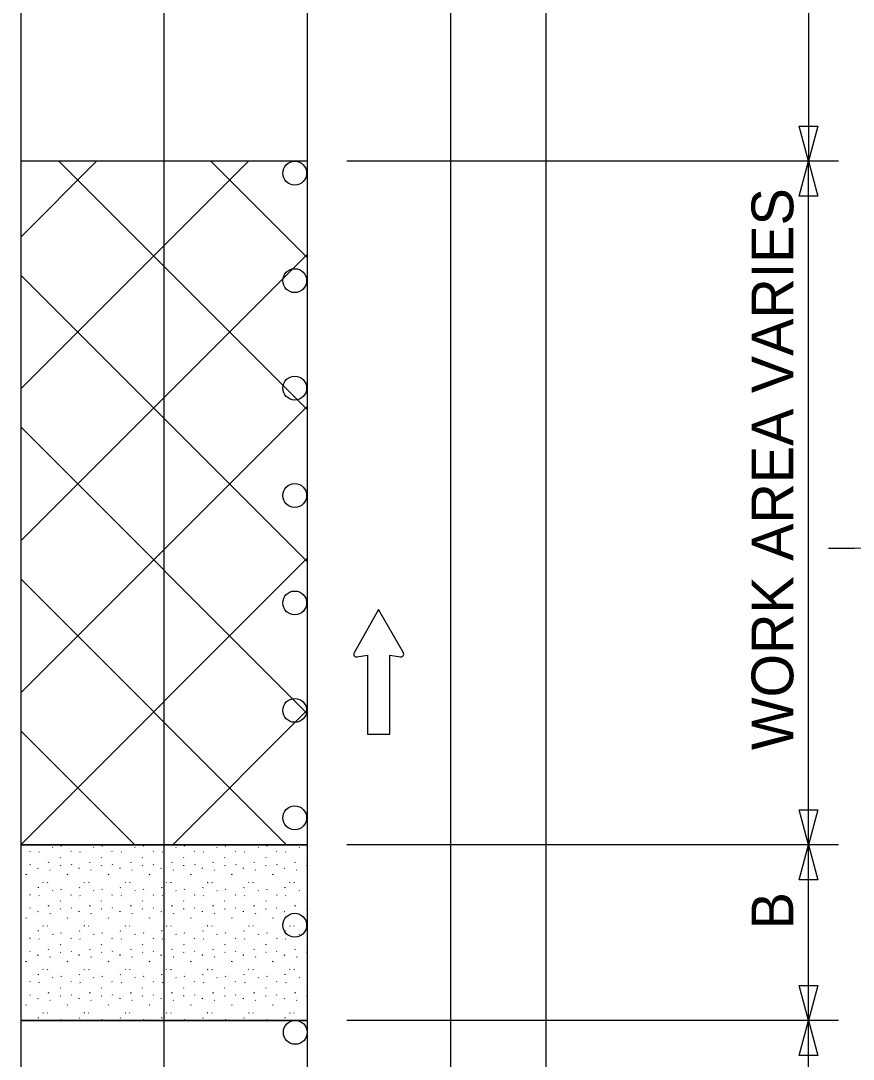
# Model space of a CAD drawing. Extents: x 16553 to 18478, y 5759 to 7026.
# Drawn here: x 16887.7 to 17027.1, y 6687.7 to 6861.7 of the extents above; entities that cross this region are included whole.
import ezdxf

# ---------------------------------------------------------------- set-up
doc = ezdxf.new("R2010")
doc.units = 0
for name, color, linetype in [('ALI_LEGAL_EX', 7, 'Continuous'), ('MT_SCRATCH_LEVEL_A', 7, 'Continuous'), ('MT_SCRATCH_LEVEL_E', 7, 'Continuous'), ('PAVT_EDGE_EX', 7, 'Continuous'), ('TRAFFIC_SIGNS_PR', 7, 'Continuous'), ('TYPICAL_TEXT_DIMEN_PR', 7, 'Continuous')]:
    doc.layers.add(name, color=color, linetype=linetype)

msp = doc.modelspace()

# ---------------------------------------------------------------- linework, layer by layer
at = {"layer": 'ALI_LEGAL_EX'}
for p, q in [((16911.66, 7026.35), (16911.66, 6197.16)), ((16935.66, 7026.35), (16935.66, 6197.16)), ((16935.66, 7026.35), (16935.66, 6197.16))]:
    msp.add_line(p, q, dxfattribs=at)
for points in [[(16911.66, 6826.35), (16911.66, 6801.35)], [(16935.66, 6826.35), (16935.66, 6801.35)], [(16911.66, 6726.35), (16911.66, 6701.35)], [(16935.66, 6726.35), (16935.66, 6701.35)]]:
    msp.add_lwpolyline(points, dxfattribs=at)
at = {"layer": 'MT_SCRATCH_LEVEL_A'}
for p, q in [((16935.66, 6838.16), (16887.66, 6838.16)), ((16935.66, 6723.62), (16887.66, 6723.62)), ((16935.66, 6694.2), (16887.66, 6694.2))]:
    msp.add_line(p, q, dxfattribs=at)
at = {"layer": 'MT_SCRATCH_LEVEL_E'}
for p, q in [((16947.62, 6763.02), (16943.51, 6755.78)), ((16951.77, 6755.78), (16947.62, 6763.02)), ((16943.99, 6755.1), (16945.77, 6755.41)), ((16945.77, 6755.41), (16945.77, 6742.15)), ((16949.51, 6742.15), (16949.51, 6755.41)), ((16949.51, 6755.41), (16951.29, 6755.1)), ((16945.77, 6742.15), (16949.51, 6742.15))]:
    msp.add_line(p, q, dxfattribs=at)
for centre, start, end in [((16943.92, 6755.56), 150.4248, 279.9638), ((16951.36, 6755.56), 260.0362, 29.7731)]:
    msp.add_arc(centre, 0.463, start, end, dxfattribs=at)
at = {"layer": 'PAVT_EDGE_EX'}
for p, q in [((16887.66, 6926.66), (16887.66, 6223.96)), ((16959.66, 6926.66), (16959.66, 6223.96)), ((16975.66, 6926.66), (16975.66, 6223.96)), ((16935.66, 6838.16), (16887.66, 6838.16)), ((16887.66, 6838.16), (16887.66, 6723.62)), ((16887.66, 6825.45), (16900.38, 6838.16)), ((16887.66, 6799.99), (16925.83, 6838.16)), ((16935.66, 6796.54), (16894.04, 6838.16)), ((16935.66, 6822), (16919.5, 6838.16)), ((16887.66, 6774.54), (16935.66, 6822.54)), ((16935.66, 6771.08), (16887.66, 6819.08)), ((16887.66, 6749.08), (16935.66, 6797.08)), ((16935.66, 6745.63), (16887.66, 6793.63)), ((16887.66, 6723.62), (16935.66, 6771.62)), ((16932.21, 6723.62), (16887.66, 6768.17)), ((16913.12, 6723.62), (16935.66, 6746.17)), ((16906.76, 6723.62), (16887.66, 6742.72)), ((16887.66, 6723.62), (16935.66, 6723.62)), ((16935.66, 6723.62), (16887.66, 6723.62)), ((16887.66, 6723.62), (16887.66, 6694.2)), ((16887.66, 6723.62), (16887.66, 6723.62)), ((16892.98, 6723.25), (16893.03, 6723.18)), ((16894.43, 6723.4), (16894.48, 6723.52)), ((16899.87, 6723.25), (16899.92, 6723.18)), ((16901.32, 6723.4), (16901.37, 6723.52)), ((16906.76, 6723.25), (16906.81, 6723.18)), ((16908.21, 6723.4), (16908.26, 6723.52)), ((16913.64, 6723.25), (16913.69, 6723.18)), ((16915.09, 6723.4), (16915.14, 6723.52)), ((16920.53, 6723.25), (16920.58, 6723.18)), ((16921.98, 6723.4), (16922.03, 6723.52)), ((16927.42, 6723.25), (16927.47, 6723.18)), ((16928.87, 6723.4), (16928.92, 6723.52)), ((16934.31, 6723.25), (16934.36, 6723.18)), ((16889.16, 6722.57), (16889.21, 6722.5)), ((16890.69, 6722.44), (16890.74, 6722.36)), ((16894.26, 6721.52), (16894.31, 6721.44)), ((16896.05, 6722.57), (16896.1, 6722.5)), ((16897.58, 6722.44), (16897.63, 6722.36)), ((16901.15, 6721.52), (16901.2, 6721.44)), ((16902.94, 6722.57), (16902.99, 6722.5)), ((16904.47, 6722.44), (16904.52, 6722.36)), ((16908.03, 6721.52), (16908.08, 6721.44)), ((16909.82, 6722.57), (16909.88, 6722.5)), ((16911.35, 6722.44), (16911.4, 6722.36)), ((16914.92, 6721.52), (16914.97, 6721.44)), ((16916.71, 6722.57), (16916.76, 6722.5)), ((16918.24, 6722.44), (16918.29, 6722.36)), ((16921.81, 6721.52), (16921.86, 6721.44)), ((16923.6, 6722.57), (16923.65, 6722.5)), ((16925.13, 6722.44), (16925.18, 6722.36)), ((16928.7, 6721.52), (16928.75, 6721.44)), ((16930.49, 6722.57), (16930.54, 6722.5)), ((16932.02, 6722.44), (16932.07, 6722.36)), ((16935.58, 6721.52), (16935.64, 6721.44)), ((16889.21, 6720.37), (16889.26, 6720.29)), ((16890.49, 6719.79), (16890.5, 6719.67)), ((16892.33, 6720.65), (16892.38, 6720.76)), ((16892.52, 6719.45), (16892.57, 6719.37)), ((16894.3, 6720.11), (16894.35, 6720.23)), ((16896.1, 6720.37), (16896.15, 6720.29)), ((16897.38, 6719.79), (16897.39, 6719.67)), ((16899.22, 6720.65), (16899.27, 6720.76)), ((16899.41, 6719.45), (16899.46, 6719.37)), ((16901.19, 6720.11), (16901.24, 6720.23)), ((16902.99, 6720.37), (16903.04, 6720.29)), ((16904.27, 6719.79), (16904.28, 6719.67)), ((16906.11, 6720.65), (16906.16, 6720.76)), ((16906.3, 6719.45), (16906.35, 6719.37)), ((16908.08, 6720.11), (16908.13, 6720.23)), ((16909.87, 6720.37), (16909.92, 6720.29)), ((16911.15, 6719.79), (16911.17, 6719.67)), ((16912.99, 6720.65), (16913.05, 6720.76)), ((16913.18, 6719.45), (16913.24, 6719.37)), ((16914.96, 6720.11), (16915.01, 6720.23)), ((16916.76, 6720.37), (16916.81, 6720.29)), ((16918.04, 6719.79), (16918.05, 6719.67)), ((16919.88, 6720.65), (16919.93, 6720.76)), ((16920.07, 6719.45), (16920.12, 6719.37)), ((16921.85, 6720.11), (16921.9, 6720.23)), ((16923.65, 6720.37), (16923.7, 6720.29)), ((16924.93, 6719.79), (16924.94, 6719.67)), ((16926.77, 6720.65), (16926.82, 6720.76)), ((16926.96, 6719.45), (16927.01, 6719.37)), ((16928.74, 6720.11), (16928.79, 6720.23)), ((16930.53, 6720.37), (16930.59, 6720.29)), ((16931.82, 6719.79), (16931.83, 6719.67)), ((16933.66, 6720.65), (16933.71, 6720.76)), ((16933.85, 6719.45), (16933.9, 6719.37)), ((16935.63, 6720.11), (16935.66, 6720.2)), ((16888.59, 6718.61), (16888.64, 6718.73)), ((16895.48, 6718.61), (16895.53, 6718.73)), ((16902.37, 6718.61), (16902.42, 6718.73)), ((16909.25, 6718.61), (16909.31, 6718.73)), ((16916.14, 6718.61), (16916.19, 6718.73)), ((16923.03, 6718.61), (16923.08, 6718.73)), ((16929.92, 6718.61), (16929.97, 6718.73)), ((16890.61, 6716.42), (16890.66, 6716.53)), ((16891.38, 6717.38), (16891.43, 6717.3)), ((16892.11, 6717.35), (16892.16, 6717.27)), ((16892.98, 6715.97), (16893.03, 6715.89)), ((16894.43, 6716.12), (16894.48, 6716.24)), ((16897.5, 6716.42), (16897.55, 6716.53)), ((16898.26, 6717.38), (16898.31, 6717.3)), ((16899, 6717.35), (16899.05, 6717.27)), ((16899.87, 6715.97), (16899.92, 6715.89)), ((16901.32, 6716.12), (16901.37, 6716.24)), ((16904.39, 6716.42), (16904.44, 6716.53)), ((16905.15, 6717.38), (16905.2, 6717.3)), ((16905.89, 6717.35), (16905.94, 6717.27)), ((16906.76, 6715.97), (16906.81, 6715.89)), ((16908.21, 6716.12), (16908.26, 6716.24)), ((16911.27, 6716.42), (16911.33, 6716.53)), ((16912.04, 6717.38), (16912.09, 6717.3)), ((16912.78, 6717.35), (16912.83, 6717.27)), ((16913.64, 6715.97), (16913.69, 6715.89)), ((16915.09, 6716.12), (16915.14, 6716.24)), ((16918.16, 6716.42), (16918.21, 6716.53)), ((16918.92, 6717.38), (16918.98, 6717.3)), ((16919.66, 6717.35), (16919.71, 6717.27)), ((16920.53, 6715.97), (16920.58, 6715.89)), ((16921.98, 6716.12), (16922.03, 6716.24)), ((16925.05, 6716.42), (16925.1, 6716.53)), ((16925.81, 6717.38), (16925.86, 6717.3)), ((16926.55, 6717.35), (16926.6, 6717.27)), ((16927.42, 6715.97), (16927.47, 6715.89)), ((16928.87, 6716.12), (16928.92, 6716.24)), ((16931.94, 6716.42), (16931.99, 6716.53)), ((16932.7, 6717.38), (16932.75, 6717.3)), ((16933.44, 6717.35), (16933.49, 6717.27)), ((16934.31, 6715.97), (16934.36, 6715.89)), ((16889.16, 6715.29), (16889.21, 6715.21)), ((16890.69, 6715.15), (16890.74, 6715.07)), ((16894.26, 6714.23), (16894.31, 6714.15)), ((16896.05, 6715.29), (16896.1, 6715.21)), ((16897.58, 6715.15), (16897.63, 6715.07)), ((16901.15, 6714.23), (16901.2, 6714.15)), ((16902.94, 6715.29), (16902.99, 6715.21)), ((16904.47, 6715.15), (16904.52, 6715.07)), ((16908.03, 6714.23), (16908.08, 6714.15)), ((16909.82, 6715.29), (16909.88, 6715.21)), ((16911.35, 6715.15), (16911.4, 6715.07)), ((16914.92, 6714.23), (16914.97, 6714.15)), ((16916.71, 6715.29), (16916.76, 6715.21)), ((16918.24, 6715.15), (16918.29, 6715.07)), ((16921.81, 6714.23), (16921.86, 6714.15)), ((16923.6, 6715.29), (16923.65, 6715.21)), ((16925.13, 6715.15), (16925.18, 6715.07)), ((16928.7, 6714.23), (16928.75, 6714.15)), ((16930.49, 6715.29), (16930.54, 6715.21)), ((16932.02, 6715.15), (16932.07, 6715.07)), ((16935.58, 6714.23), (16935.64, 6714.15)), ((16889.21, 6713.08), (16889.26, 6713)), ((16890.49, 6712.51), (16890.5, 6712.39)), ((16892.33, 6713.36), (16892.38, 6713.48)), ((16894.3, 6712.83), (16894.35, 6712.95)), ((16896.1, 6713.08), (16896.15, 6713)), ((16897.38, 6712.51), (16897.39, 6712.39)), ((16899.22, 6713.36), (16899.27, 6713.48)), ((16901.19, 6712.83), (16901.24, 6712.95)), ((16902.99, 6713.08), (16903.04, 6713)), ((16904.27, 6712.51), (16904.28, 6712.39)), ((16906.11, 6713.36), (16906.16, 6713.48)), ((16908.08, 6712.83), (16908.13, 6712.95)), ((16909.87, 6713.08), (16909.92, 6713)), ((16911.15, 6712.51), (16911.17, 6712.39)), ((16912.99, 6713.36), (16913.05, 6713.48)), ((16914.96, 6712.83), (16915.01, 6712.95)), ((16916.76, 6713.08), (16916.81, 6713)), ((16918.04, 6712.51), (16918.05, 6712.39)), ((16919.88, 6713.36), (16919.93, 6713.48)), ((16921.85, 6712.83), (16921.9, 6712.95)), ((16923.65, 6713.08), (16923.7, 6713)), ((16924.93, 6712.51), (16924.94, 6712.39)), ((16926.77, 6713.36), (16926.82, 6713.48)), ((16928.74, 6712.83), (16928.79, 6712.95)), ((16930.53, 6713.08), (16930.59, 6713)), ((16931.82, 6712.51), (16931.83, 6712.39)), ((16933.66, 6713.36), (16933.71, 6713.48)), ((16935.63, 6712.83), (16935.66, 6712.92)), ((16888.59, 6711.33), (16888.64, 6711.44)), ((16892.52, 6712.16), (16892.57, 6712.08)), ((16895.48, 6711.33), (16895.53, 6711.44)), ((16899.41, 6712.16), (16899.46, 6712.08)), ((16902.37, 6711.33), (16902.42, 6711.44)), ((16906.3, 6712.16), (16906.35, 6712.08)), ((16909.25, 6711.33), (16909.31, 6711.44)), ((16913.18, 6712.16), (16913.24, 6712.08)), ((16916.14, 6711.33), (16916.19, 6711.44)), ((16920.07, 6712.16), (16920.12, 6712.08)), ((16923.03, 6711.33), (16923.08, 6711.44)), ((16926.96, 6712.16), (16927.01, 6712.08)), ((16929.92, 6711.33), (16929.97, 6711.44)), ((16933.85, 6712.16), (16933.9, 6712.08)), ((16890.61, 6709.13), (16890.66, 6709.25)), ((16891.38, 6710.09), (16891.43, 6710.01)), ((16892.11, 6710.06), (16892.16, 6709.98)), ((16894.43, 6708.83), (16894.48, 6708.95)), ((16897.5, 6709.13), (16897.55, 6709.25)), ((16898.26, 6710.09), (16898.31, 6710.01)), ((16899, 6710.06), (16899.05, 6709.98)), ((16901.32, 6708.83), (16901.37, 6708.95)), ((16904.39, 6709.13), (16904.44, 6709.25)), ((16905.15, 6710.09), (16905.2, 6710.01)), ((16905.89, 6710.06), (16905.94, 6709.98)), ((16908.21, 6708.83), (16908.26, 6708.95)), ((16911.27, 6709.13), (16911.33, 6709.25)), ((16912.04, 6710.09), (16912.09, 6710.01)), ((16912.78, 6710.06), (16912.83, 6709.98)), ((16915.09, 6708.83), (16915.14, 6708.95)), ((16918.16, 6709.13), (16918.21, 6709.25)), ((16918.92, 6710.09), (16918.98, 6710.01)), ((16919.66, 6710.06), (16919.71, 6709.98)), ((16921.98, 6708.83), (16922.03, 6708.95)), ((16925.05, 6709.13), (16925.1, 6709.25)), ((16925.81, 6710.09), (16925.86, 6710.01)), ((16926.55, 6710.06), (16926.6, 6709.98)), ((16928.87, 6708.83), (16928.92, 6708.95)), ((16931.94, 6709.13), (16931.99, 6709.25)), ((16932.7, 6710.09), (16932.75, 6710.01)), ((16933.44, 6710.06), (16933.49, 6709.98)), ((16889.16, 6708.01), (16889.21, 6707.93)), ((16890.69, 6707.86), (16890.74, 6707.79)), ((16892.98, 6708.68), (16893.03, 6708.61)), ((16896.05, 6708.01), (16896.1, 6707.93)), ((16897.58, 6707.86), (16897.63, 6707.79)), ((16899.87, 6708.68), (16899.92, 6708.61)), ((16902.94, 6708.01), (16902.99, 6707.93)), ((16904.47, 6707.86), (16904.52, 6707.79)), ((16906.76, 6708.68), (16906.81, 6708.61)), ((16909.82, 6708.01), (16909.88, 6707.93)), ((16911.35, 6707.86), (16911.4, 6707.79)), ((16913.64, 6708.68), (16913.69, 6708.61)), ((16916.71, 6708.01), (16916.76, 6707.93)), ((16918.24, 6707.86), (16918.29, 6707.79)), ((16920.53, 6708.68), (16920.58, 6708.61)), ((16923.6, 6708.01), (16923.65, 6707.93)), ((16925.13, 6707.86), (16925.18, 6707.79)), ((16927.42, 6708.68), (16927.47, 6708.61)), ((16930.49, 6708.01), (16930.54, 6707.93)), ((16932.02, 6707.86), (16932.07, 6707.79)), ((16934.31, 6708.68), (16934.36, 6708.61)), ((16889.21, 6705.8), (16889.26, 6705.72)), ((16892.33, 6706.08), (16892.38, 6706.19)), ((16894.26, 6706.95), (16894.31, 6706.87)), ((16894.3, 6705.55), (16894.35, 6705.66)), ((16896.1, 6705.8), (16896.15, 6705.72)), ((16899.22, 6706.08), (16899.27, 6706.19)), ((16901.15, 6706.95), (16901.2, 6706.87)), ((16901.19, 6705.55), (16901.24, 6705.66)), ((16902.99, 6705.8), (16903.04, 6705.72)), ((16906.11, 6706.08), (16906.16, 6706.19)), ((16908.03, 6706.95), (16908.08, 6706.87)), ((16908.08, 6705.55), (16908.13, 6705.66)), ((16909.87, 6705.8), (16909.92, 6705.72)), ((16912.99, 6706.08), (16913.05, 6706.19)), ((16914.92, 6706.95), (16914.97, 6706.87)), ((16914.96, 6705.55), (16915.01, 6705.66)), ((16916.76, 6705.8), (16916.81, 6705.72)), ((16919.88, 6706.08), (16919.93, 6706.19)), ((16921.81, 6706.95), (16921.86, 6706.87)), ((16921.85, 6705.55), (16921.9, 6705.66)), ((16923.65, 6705.8), (16923.7, 6705.72)), ((16926.77, 6706.08), (16926.82, 6706.19)), ((16928.7, 6706.95), (16928.75, 6706.87)), ((16928.74, 6705.55), (16928.79, 6705.66)), ((16930.53, 6705.8), (16930.59, 6705.72)), ((16933.66, 6706.08), (16933.71, 6706.19)), ((16935.58, 6706.95), (16935.64, 6706.87)), ((16935.63, 6705.55), (16935.66, 6705.63)), ((16888.59, 6704.04), (16888.64, 6704.16)), ((16890.49, 6705.22), (16890.5, 6705.1)), ((16892.52, 6704.88), (16892.57, 6704.8)), ((16895.48, 6704.04), (16895.53, 6704.16)), ((16897.38, 6705.22), (16897.39, 6705.1)), ((16899.41, 6704.88), (16899.46, 6704.8)), ((16902.37, 6704.04), (16902.42, 6704.16)), ((16904.27, 6705.22), (16904.28, 6705.1)), ((16906.3, 6704.88), (16906.35, 6704.8)), ((16909.25, 6704.04), (16909.31, 6704.16)), ((16911.15, 6705.22), (16911.17, 6705.1)), ((16913.18, 6704.88), (16913.24, 6704.8)), ((16916.14, 6704.04), (16916.19, 6704.16)), ((16918.04, 6705.22), (16918.05, 6705.1)), ((16920.07, 6704.88), (16920.12, 6704.8)), ((16923.03, 6704.04), (16923.08, 6704.16)), ((16924.93, 6705.22), (16924.94, 6705.1)), ((16926.96, 6704.88), (16927.01, 6704.8)), ((16929.92, 6704.04), (16929.97, 6704.16)), ((16931.82, 6705.22), (16931.83, 6705.1)), ((16933.85, 6704.88), (16933.9, 6704.8)), ((16891.38, 6702.81), (16891.43, 6702.73)), ((16892.11, 6702.78), (16892.16, 6702.7)), ((16898.26, 6702.81), (16898.31, 6702.73)), ((16899, 6702.78), (16899.05, 6702.7)), ((16905.15, 6702.81), (16905.2, 6702.73)), ((16905.89, 6702.78), (16905.94, 6702.7)), ((16912.04, 6702.81), (16912.09, 6702.73)), ((16912.78, 6702.78), (16912.83, 6702.7)), ((16918.92, 6702.81), (16918.98, 6702.73)), ((16919.66, 6702.78), (16919.71, 6702.7)), ((16925.81, 6702.81), (16925.86, 6702.73)), ((16926.55, 6702.78), (16926.6, 6702.7)), ((16932.7, 6702.81), (16932.75, 6702.73)), ((16933.44, 6702.78), (16933.49, 6702.7)), ((16889.16, 6700.72), (16889.21, 6700.64)), ((16890.61, 6701.85), (16890.66, 6701.96)), ((16890.69, 6700.58), (16890.74, 6700.5)), ((16892.98, 6701.4), (16893.03, 6701.32)), ((16894.43, 6701.55), (16894.48, 6701.67)), ((16896.05, 6700.72), (16896.1, 6700.64)), ((16897.5, 6701.85), (16897.55, 6701.96)), ((16897.58, 6700.58), (16897.63, 6700.5)), ((16899.87, 6701.4), (16899.92, 6701.32)), ((16901.32, 6701.55), (16901.37, 6701.67)), ((16902.94, 6700.72), (16902.99, 6700.64)), ((16904.39, 6701.85), (16904.44, 6701.96)), ((16904.47, 6700.58), (16904.52, 6700.5)), ((16906.76, 6701.4), (16906.81, 6701.32)), ((16908.21, 6701.55), (16908.26, 6701.67)), ((16909.82, 6700.72), (16909.88, 6700.64)), ((16911.27, 6701.85), (16911.33, 6701.96)), ((16911.35, 6700.58), (16911.4, 6700.5)), ((16913.64, 6701.4), (16913.69, 6701.32)), ((16915.09, 6701.55), (16915.14, 6701.67)), ((16916.71, 6700.72), (16916.76, 6700.64)), ((16918.16, 6701.85), (16918.21, 6701.96)), ((16918.24, 6700.58), (16918.29, 6700.5)), ((16920.53, 6701.4), (16920.58, 6701.32)), ((16921.98, 6701.55), (16922.03, 6701.67)), ((16923.6, 6700.72), (16923.65, 6700.64)), ((16925.05, 6701.85), (16925.1, 6701.96)), ((16925.13, 6700.58), (16925.18, 6700.5)), ((16927.42, 6701.4), (16927.47, 6701.32)), ((16928.87, 6701.55), (16928.92, 6701.67)), ((16930.49, 6700.72), (16930.54, 6700.64)), ((16931.94, 6701.85), (16931.99, 6701.96)), ((16932.02, 6700.58), (16932.07, 6700.5)), ((16934.31, 6701.4), (16934.36, 6701.32)), ((16889.21, 6698.51), (16889.26, 6698.43)), ((16892.33, 6698.79), (16892.38, 6698.91)), ((16894.26, 6699.66), (16894.31, 6699.58)), ((16896.1, 6698.51), (16896.15, 6698.43)), ((16899.22, 6698.79), (16899.27, 6698.91)), ((16901.15, 6699.66), (16901.2, 6699.58)), ((16902.99, 6698.51), (16903.04, 6698.43)), ((16906.11, 6698.79), (16906.16, 6698.91)), ((16908.03, 6699.66), (16908.08, 6699.58)), ((16909.87, 6698.51), (16909.92, 6698.43)), ((16912.99, 6698.79), (16913.05, 6698.91)), ((16914.92, 6699.66), (16914.97, 6699.58)), ((16916.76, 6698.51), (16916.81, 6698.43)), ((16919.88, 6698.79), (16919.93, 6698.91)), ((16921.81, 6699.66), (16921.86, 6699.58)), ((16923.65, 6698.51), (16923.7, 6698.43)), ((16926.77, 6698.79), (16926.82, 6698.91)), ((16928.7, 6699.66), (16928.75, 6699.58)), ((16930.53, 6698.51), (16930.59, 6698.43)), ((16933.66, 6698.79), (16933.71, 6698.91)), ((16935.58, 6699.66), (16935.64, 6699.58)), ((16888.59, 6696.76), (16888.64, 6696.88)), ((16890.49, 6697.94), (16890.5, 6697.82)), ((16892.52, 6697.59), (16892.57, 6697.51)), ((16894.3, 6698.26), (16894.35, 6698.38)), ((16895.48, 6696.76), (16895.53, 6696.88)), ((16897.38, 6697.94), (16897.39, 6697.82)), ((16899.41, 6697.59), (16899.46, 6697.51)), ((16901.19, 6698.26), (16901.24, 6698.38)), ((16902.37, 6696.76), (16902.42, 6696.88)), ((16904.27, 6697.94), (16904.28, 6697.82)), ((16906.3, 6697.59), (16906.35, 6697.51)), ((16908.08, 6698.26), (16908.13, 6698.38)), ((16909.25, 6696.76), (16909.31, 6696.88)), ((16911.15, 6697.94), (16911.17, 6697.82)), ((16913.18, 6697.59), (16913.24, 6697.51)), ((16914.96, 6698.26), (16915.01, 6698.38)), ((16916.14, 6696.76), (16916.19, 6696.88)), ((16918.04, 6697.94), (16918.05, 6697.82)), ((16920.07, 6697.59), (16920.12, 6697.51)), ((16921.85, 6698.26), (16921.9, 6698.38)), ((16923.03, 6696.76), (16923.08, 6696.88)), ((16924.93, 6697.94), (16924.94, 6697.82)), ((16926.96, 6697.59), (16927.01, 6697.51)), ((16928.74, 6698.26), (16928.79, 6698.38)), ((16929.92, 6696.76), (16929.97, 6696.88)), ((16931.82, 6697.94), (16931.83, 6697.82)), ((16933.85, 6697.59), (16933.9, 6697.51)), ((16935.63, 6698.26), (16935.66, 6698.35)), ((16891.38, 6695.52), (16891.43, 6695.44)), ((16892.11, 6695.49), (16892.16, 6695.41)), ((16898.26, 6695.52), (16898.31, 6695.44)), ((16899, 6695.49), (16899.05, 6695.41)), ((16905.15, 6695.52), (16905.2, 6695.44)), ((16905.89, 6695.49), (16905.94, 6695.41)), ((16912.04, 6695.52), (16912.09, 6695.44)), ((16912.78, 6695.49), (16912.83, 6695.41)), ((16918.92, 6695.52), (16918.98, 6695.44)), ((16919.66, 6695.49), (16919.71, 6695.41)), ((16925.81, 6695.52), (16925.86, 6695.44)), ((16926.55, 6695.49), (16926.6, 6695.41)), ((16932.7, 6695.52), (16932.75, 6695.44)), ((16933.44, 6695.49), (16933.49, 6695.41)), ((16887.66, 6694.2), (16935.66, 6694.2)), ((16890.61, 6694.56), (16890.66, 6694.68)), ((16894.43, 6694.26), (16894.48, 6694.38)), ((16897.5, 6694.56), (16897.55, 6694.68)), ((16901.32, 6694.26), (16901.37, 6694.38)), ((16904.39, 6694.56), (16904.44, 6694.68)), ((16908.21, 6694.26), (16908.26, 6694.38)), ((16911.27, 6694.56), (16911.33, 6694.68)), ((16915.09, 6694.26), (16915.14, 6694.38)), ((16918.16, 6694.56), (16918.21, 6694.68)), ((16921.98, 6694.26), (16922.03, 6694.38)), ((16925.05, 6694.56), (16925.1, 6694.68)), ((16928.87, 6694.26), (16928.92, 6694.38)), ((16931.94, 6694.56), (16931.99, 6694.68))]:
    msp.add_line(p, q, dxfattribs=at)
at = {"layer": 'TRAFFIC_SIGNS_PR'}
for centre in [(16933.56, 6836.14), (16933.56, 6818.14), (16933.56, 6800.14), (16933.56, 6782.14), (16933.56, 6764.14), (16933.56, 6746.14), (16933.56, 6728.14), (16933.56, 6710.14), (16933.66, 6692.2)]:
    msp.add_circle(centre, 2, dxfattribs=at)
at = {"layer": 'TYPICAL_TEXT_DIMEN_PR'}
for p, q in [((17019.66, 6888.16), (17019.66, 6838.16)), ((17019.66, 6838.16), (17018.09, 6844.02)), ((17018.09, 6844.02), (17019.66, 6844.02)), ((17019.66, 6844.02), (17021.23, 6844.02)), ((17021.23, 6844.02), (17019.66, 6838.16)), ((17024.66, 6838.16), (16942.27, 6838.16)), ((17018.09, 6832.3), (17019.66, 6838.16)), ((17019.66, 6723.62), (17019.66, 6838.16)), ((17019.66, 6838.16), (17021.23, 6832.3)), ((17019.66, 6832.3), (17018.09, 6832.3)), ((17021.23, 6832.3), (17019.66, 6832.3)), ((17019.66, 6723.62), (17018.09, 6729.49)), ((17018.09, 6729.49), (17019.66, 6729.49)), ((17019.66, 6729.49), (17021.23, 6729.49)), ((17021.23, 6729.49), (17019.66, 6723.62)), ((17024.66, 6723.62), (16942.27, 6723.62)), ((17018.09, 6717.76), (17019.66, 6723.62)), ((17019.66, 6694.2), (17019.66, 6723.62)), ((17019.66, 6723.62), (17021.23, 6717.76)), ((17019.66, 6717.76), (17018.09, 6717.76)), ((17021.23, 6717.76), (17019.66, 6717.76)), ((17019.66, 6694.2), (17018.09, 6700.06)), ((17018.09, 6700.06), (17019.66, 6700.06)), ((17019.66, 6700.06), (17021.23, 6700.06)), ((17021.23, 6700.06), (17019.66, 6694.2)), ((17024.66, 6694.2), (16942.27, 6694.2)), ((17018.09, 6688.34), (17019.66, 6694.2)), ((17019.66, 6663.63), (17019.66, 6694.2)), ((17019.66, 6694.2), (17021.23, 6688.34)), ((17019.66, 6688.34), (17018.09, 6688.34)), ((17021.23, 6688.34), (17019.66, 6688.34))]:
    msp.add_line(p, q, dxfattribs=at)
msp.add_open_spline([(17022.97, 6773.31), (17071.44, 6773.31), (17071.44, 6784.07), (17036.52, 6784.07), (17036.52, 6793.11), (17070.73, 6794.88), (17079.02, 6795.17)], degree=3, dxfattribs=at)

# ---------------------------------------------------------------- texts
for s, p in [('WORK AREA VARIES', (17017.1, 6739.48)), ('B', (17017.1, 6709.46))]:
    msp.add_text(s, height=7, rotation=90, dxfattribs=at).set_placement(p)

doc.saveas('drawing.dxf')
